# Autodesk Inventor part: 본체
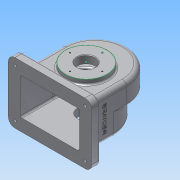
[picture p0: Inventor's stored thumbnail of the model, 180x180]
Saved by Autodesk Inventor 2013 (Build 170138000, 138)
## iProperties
Created: 2017-11
Part Number: 본체
Material: 알루미늄 6061
Document SubType Name: Modeling
Designer: Administrator
Density: 2.71 g/cm^3
Mass: 1079.49 g
Surface Area: 1182.07 cm^2
Volume: 398.334 cm^3
Author: Administrator
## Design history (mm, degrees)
sketch "스케치2"
  geometry: L1 (-75, -50)-(75, -50); L2 (75, -50)-(75, -65); L3 (75, -65)-(-75, -65); L4 (-75, -65)-(-75, -50); L5 (-58, 15)-(-58, -50); L6 (58, 15)-(58, -50); A1 r 58 centre (0, 15) between (58, 15) and (-58, 15); 2 further points
  constraints: 12 end point, 3 perpendicular, 2 parallel, 2 point on circle, 2 point on line, 2 tangent, 2 vertical alignment, 1 centre point, 1 horizontal, 1 midpoint
  dimensions: "d6" = 116 diameter of A1; "d7" = 150 distance of L2.end L3.end; "d8" = 15 distance of L3.end L1.start; "d9" = 65 distance from line of point (0, 0) L3; "d10" = 80 distance from line of A1.centre L3
extrude "돌출2" new body sketch "스케치2" stored distance "d11" = 110; taper "d12" = 0 deg
extrude "돌출3" join sketch "스케치2" distance "d13" = 38; taper "d14" = 0 deg
sketch "스케치3"
  geometry: L1 (58, 15)-(58, -50) reference; L2 (-58, -50)-(-58, 15) reference; L3 (58, -50)-(-58, -50) reference; L4 (-58, -8)-(-58, -50); L5 (58, -8)-(58, -50); L6 (-75, -65)-(75, -65) reference; A1 r 58 centre (0, -8) between (58, -8) and (-58, -8); A2 r 52.126 centre (0, -8) between (-30.872, -50) and (30.872, -50)
  constraints: 4 end point, 4 point on circle, 4 point on line, 2 centre point, 2 collinear
  dimensions: "d18" = 58 radius of A1; "d91" = 57 distance from line of L6 A1.centre
extrude "돌출4" join sketch "스케치3" distance "d19" = 38; taper "d20" = 0 deg
feature "쉘1" dims "d22" = 1000, "d23" = 5
fillet "모깎기2" dims "d24" = 12
node "작업 평면4"
  node "작업 평면3"
sketch "스케치4"
  geometry: L1 (58, 38)-(-58, 38) reference; C1 r 6 at (0, 19); 1 further point
  constraints: 1 centre point, 1 vertical alignment
  dimensions: "d27" = 12 diameter of C1; "d29" = 19 distance from line of C1.centre L1
extrude "돌출5" join sketch "스케치4" stored distance "d30" = 10; taper "d31" = 0 deg
sketch "스케치5"
  geometry: C1 r 6 at (0, 0) reference; 1 further point
hole "구멍1" sketch "스케치5" at (0, 0) diameter "d32" = 4.459; stored, may be unused: countersink angle "d36" = 90 deg, drill point angle "d38" = 0 deg; dims "d33" = 6, "d34" = 4, "d35" = 2, "d37" = 8
sketch "스케치7"
  geometry: C1 r 37.5 at (0, 0); 1 further point
  constraints: 1 centre point, 1 coincident
  dimensions: "d42" = 75 diameter of C1
extrude "돌출7" join sketch "스케치7" distance "d43" = 9; taper "d44" = 0 deg
sketch "스케치11"
  geometry: L1 (0, 0)-(0, 29); C1 r 37.5 at (0, 0) reference
  constraints: 2 end point, 1 vertical
  dimensions: "d62" = 29 distance of L1.start L1.end
hole "구멍3" sketch "스케치11" at (0, 29) diameter "d63" = 2.459; stored, may be unused: countersink angle "d67" = 90 deg, drill point angle "d69" = 118 deg; dims "d64" = 6, "d65" = 4, "d66" = 2, "d68" = 8
sketch "스케치12"
  geometry: A1 r 12 centre (126, 12) between (126, 0) and (138, 12) reference; 1 further point
hole "구멍4" sketch "스케치12" at (126, 12) diameter "d73" = 5; stored, may be unused: countersink angle "d77" = 90 deg, drill point angle "d79" = 0 deg; dims "d74" = 6, "d75" = 12, "d76" = 5, "d78" = 8
fillet "모깎기3" dims "d80" = 3
fillet "모깎기4" dims "d81" = 8
fillet "모깎기6" dims "d83" = 3
fillet "모깎기7" dims "d87" = 3
sketch "스케치13"
  geometry: L1 (46, -57)-(-40, -57) reference; L2 (-35, 23)-(-35, -39) reference; 2 further points
  constraints: 1 vertical alignment, 1 other
  dimensions: "d88" = 40 distance from line of point (3, -17) L1
feature "엠보싱1" sketch "스케치13" dims "d18" = 58, "d89" = 0.5, "d90" = 0, "d91" = 57
sketch "스케치14"
  geometry: C1 r 1.23 at (0, 29) reference; C2 r 37.5 at (0, 0) reference
sketch "스케치15"
  geometry: C1 r 37.5 at (0, 0) reference; C2 r 16 at (0, 0)
  constraints: 1 centre point, 1 coincident
  dimensions: "d92" = 32 diameter of C2
extrude "돌출10" cut sketch "스케치15" stored distance "d93" = 10; taper "d94" = 0 deg
sketch "스케치16"
  geometry: C1 r 31 at (0, 0); 1 further point
  constraints: 1 centre point, 1 coincident
  dimensions: "d95" = 62 diameter of C1
extrude "돌출11" join sketch "스케치16" distance "d96" = 10; taper "d97" = 0 deg
sketch "스케치17"
  geometry: C1 r 31 at (0, 0) reference; C2 r 16 at (0, 0)
  constraints: 1 centre point, 1 coincident
  dimensions: "d98" = 32 diameter of C2
extrude "돌출12" cut sketch "스케치17" stored distance "d99" = 10; taper "d100" = 0 deg
chamfer "모따기2" distance "d101" = 1; stored, may be unused: second distance "d102" = 2, angle "d103" = 45 deg
sketch "스케치18"
  geometry: L1 (0, 0)-(0, 26); C1 r 17 at (0, 0) reference
  constraints: 2 end point, 1 vertical
  dimensions: "d107" = 26 distance of L1.start L1.end
hole "구멍5" sketch "스케치18" at (0, 26) diameter "d108" = 2.459; stored, may be unused: countersink angle "d112" = 90 deg, drill point angle "d114" = 118 deg; dims "d109" = 6, "d110" = 12, "d111" = 5, "d113" = 8
fillet "모깎기8" dims "d118" = 3
node "솔리드2"
mirror "대칭1"
mirror "대칭2"
pattern_circular "원형 패턴3" dims angle "d105" = 360 deg
pattern_circular "원형 패턴4" dims angle "d116" = 360 deg
other parameters: "d17" = 116, "d26" = 6
